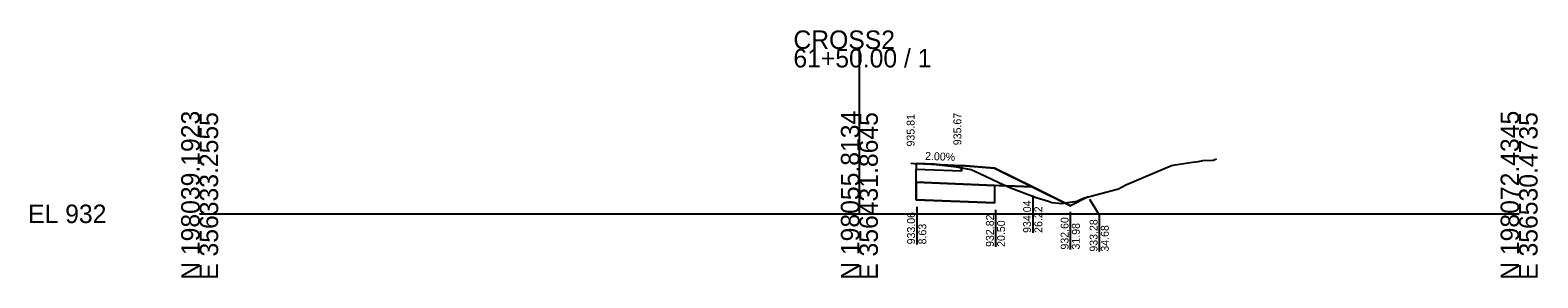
# Model space of a CAD drawing. Extents: x -26 to 203, y -10 to 14021.
# Drawn here: x -25.7 to 202.8, y 2490.3 to 2527.8 of the extents above; entities that cross this region are included whole.
import ezdxf

# ---------------------------------------------------------------- set-up
doc = ezdxf.new("R2010")
doc.units = 0
for name, color, linetype in [('Default', 7, 'Continuous'), ('P_E_XS_Ground', 7, 'Continuous'), ('P_XS', 7, 'Continuous'), ('P_XS_EAR_CommonGrnd', 7, 'Continuous'), ('P_XS_Lane', 7, 'Continuous'), ('P_XS_Rock', 7, 'Continuous')]:
    doc.layers.add(name, color=color, linetype=linetype)

msp = doc.modelspace()

# ---------------------------------------------------------------- linework, layer by layer
at = {"layer": 'Default'}
for p, q in [((100, 2500), (100, 2524.97)), ((0, 2500), (100, 2500)), ((100, 2500), (200, 2500))]:
    msp.add_line(p, q, dxfattribs=at)
at = {"layer": 'P_E_XS_Ground'}
for p, q in [((107.82, 2507.65), (108.31, 2507.62)), ((108.31, 2507.62), (110.76, 2507.56)), ((110.76, 2507.56), (111.19, 2507.52)), ((111.19, 2507.52), (114.3, 2507.16)), ((114.3, 2507.16), (114.65, 2507.1)), ((114.65, 2507.1), (116.92, 2506.72)), ((140.39, 2504.41), (147.31, 2507.32)), ((147.31, 2507.32), (147.85, 2507.43)), ((147.85, 2507.43), (150.48, 2507.82)), ((150.48, 2507.82), (151.41, 2507.93)), ((151.41, 2507.93), (152.05, 2508.08)), ((152.05, 2508.08), (153.64, 2508.14)), ((153.64, 2508.14), (154.13, 2508.32)), ((116.92, 2506.72), (118.26, 2506.11)), ((118.26, 2506.11), (121.9, 2504.39)), ((121.9, 2504.39), (122.83, 2503.99)), ((122.83, 2503.99), (126.8, 2502.45)), ((126.8, 2502.45), (128.66, 2501.92)), ((133.95, 2502.36), (135.86, 2502.87)), ((135.86, 2502.87), (139.27, 2503.8)), ((139.27, 2503.8), (140.39, 2504.41)), ((128.66, 2501.92), (129.18, 2501.74)), ((129.18, 2501.74), (130.22, 2501.59)), ((130.22, 2501.59), (130.71, 2501.58)), ((130.71, 2501.58), (132.32, 2501.81)), ((132.32, 2501.81), (132.98, 2501.91)), ((132.98, 2501.91), (133.95, 2502.36))]:
    msp.add_line(p, q, dxfattribs=at)
at = {"layer": 'P_XS'}
for p, q in [((108.63, 2507.61), (108.63, 2506.78)), ((115.5, 2507.34), (115.5, 2506.5)), ((108.63, 2506.78), (115.5, 2506.51)), ((108.63, 2504.78), (108.63, 2506.78)), ((108.63, 2504.78), (126.22, 2504.08)), ((108.63, 2504.78), (108.63, 2502.11)), ((120.5, 2504.31), (120.5, 2501.64)), ((108.63, 2502.11), (120.5, 2501.64))]:
    msp.add_line(p, q, dxfattribs=at)
at = {"layer": 'P_XS_EAR_CommonGrnd'}
for points in [[(111.19, 2507.52), (111.33, 2507.51), (108.63, 2507.61), (110.76, 2507.56)], [(108.63, 2506.78), (115.5, 2506.51), (115.5, 2506.96), (114.65, 2507.1), (114.3, 2507.16), (111.33, 2507.51), (108.63, 2507.61)], [(111.33, 2507.51), (115.5, 2507.34), (115.5, 2506.96), (114.65, 2507.1), (114.3, 2507.16)], [(118.26, 2506.11), (121.9, 2504.39), (122.26, 2504.24), (126.22, 2504.08), (120.5, 2506.94), (115.5, 2507.34), (115.5, 2506.96), (116.92, 2506.72)], [(118.26, 2506.11), (121.9, 2504.39), (122.26, 2504.24), (120.5, 2504.31), (108.63, 2504.78), (108.63, 2506.78), (115.5, 2506.51), (115.5, 2506.96), (116.92, 2506.72)], [(108.63, 2504.78), (120.5, 2504.31), (120.5, 2501.64), (108.63, 2502.11)], [(122.26, 2504.24), (122.83, 2503.99), (126.8, 2502.45), (128.66, 2501.92), (129.18, 2501.74), (130.22, 2501.59), (130.71, 2501.58), (131.1, 2501.64), (126.22, 2504.08)], [(132.32, 2501.81), (132.98, 2501.91), (133.95, 2502.36), (134.68, 2502.55), (131.98, 2501.2), (131.1, 2501.64)]]:
    msp.add_lwpolyline(points, close=True, dxfattribs=at)
at = {"layer": 'P_XS_Lane'}
for p, q in [((108.63, 2507.61), (115.5, 2507.34)), ((115.5, 2507.34), (120.5, 2506.94)), ((120.5, 2506.94), (131.98, 2501.2)), ((134.68, 2502.55), (131.98, 2501.2))]:
    msp.add_line(p, q, dxfattribs=at)
at = {"layer": 'P_XS_Rock'}
for p, q in [((126.27, 2502.8), (126.27, 2497.11)), ((108.69, 2501.05), (108.69, 2495.36)), ((120.63, 2500.59), (120.63, 2494.99)), ((131.96, 2500.28), (131.96, 2494.59)), ((134.9, 2502.2), (136.35, 2499.87)), ((136.35, 2499.87), (136.35, 2494.27))]:
    msp.add_line(p, q, dxfattribs=at)

# ---------------------------------------------------------------- texts
at = {"layer": 'Default'}
for s, p in [('CROSS2', (90, 2524.97)), ('61+50.00 / 1', (90, 2522.17)), ('EL 932', (-26, 2498.6))]:
    msp.add_text(s, height=2.8, dxfattribs=at).set_placement(p)
for s, p in [('N 198039.1923', (0, 2490)), ('E 356333.2555', (2.8, 2490)), ('N 198055.8134', (100, 2490)), ('E 356431.8645', (102.8, 2490)), ('N 198072.4345', (200, 2490)), ('E 356530.4735', (202.8, 2490))]:
    msp.add_text(s, height=2.8, rotation=90, dxfattribs=at).set_placement(p)
at = {"layer": 'P_XS_Rock'}
for s, rotation, p in [('935.81', 90, (108.37, 2510.2)), ('935.67', 90, (115.45, 2510.39)), ('2.00%', 357.7094, (109.94, 2508.18)), ('933.06', 90, (108.44, 2495.37)), ('934.04', 90, (126.02, 2497.11)), ('26.22', 90, (127.72, 2497.11)), ('8.63', 90, (110.14, 2495.37)), ('932.82', 90, (120.38, 2494.99)), ('20.50', 90, (122.08, 2494.99)), ('932.60', 90, (131.71, 2494.59)), ('31.98', 90, (133.41, 2494.59)), ('933.28', 90, (136.1, 2494.27)), ('34.68', 90, (137.8, 2494.27))]:
    msp.add_text(s, height=1.2, rotation=rotation, dxfattribs=at).set_placement(p)

doc.saveas('drawing.dxf')
